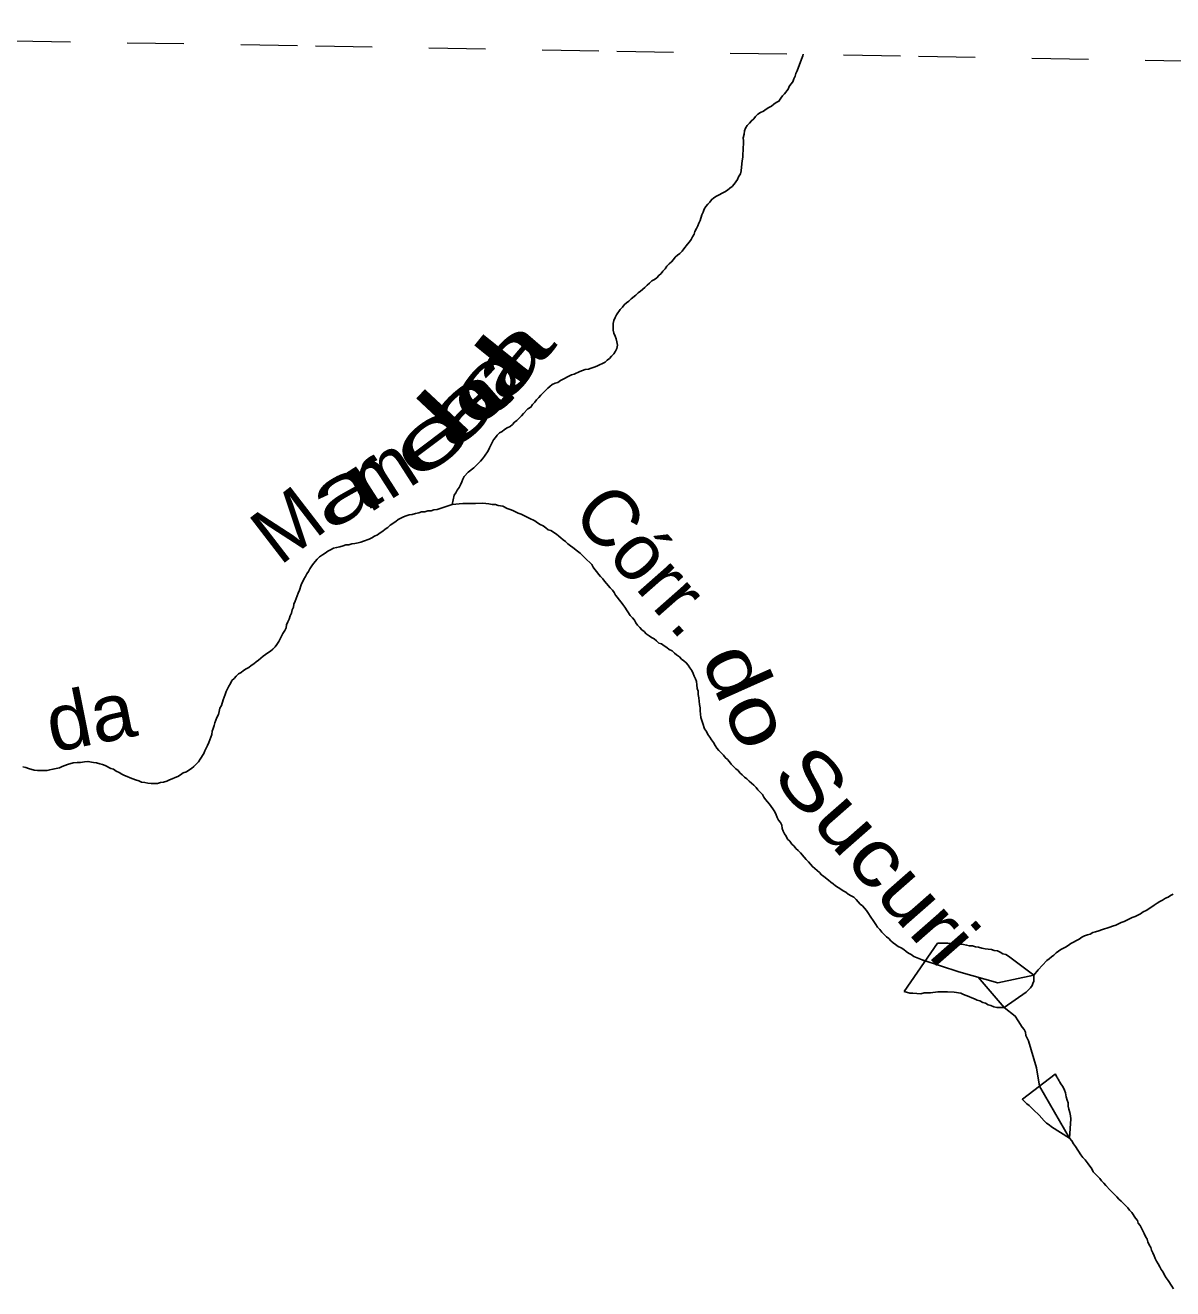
# Model space of a CAD drawing. Extents: x 785.9 to 812.4, y 7674.9 to 7703.1.
# Drawn here: x 787.987 to 790.01, y 7700.827 to 7703.055 of the extents above; entities that cross this region are included whole.
import ezdxf
from ezdxf.enums import TextEntityAlignment as Align

# ---------------------------------------------------------------- set-up
doc = ezdxf.new("R2010")
doc.units = 0
doc.header["$LTSCALE"] = 0.04
doc.linetypes.add('SHORT_DASHED', pattern=[2.7, 1.5, -1.2])
for name, color, linetype, lineweight in [('2', 7, 'Continuous', 25), ('53', 7, 'SHORT_DASHED', 13), ('55', 7, 'Continuous', 25), ('7', 7, 'Continuous', 25)]:
    doc.layers.add(name, color=color, linetype=linetype, lineweight=lineweight)
doc.layers.add('61', color=7, linetype='Continuous')

msp = doc.modelspace()

# ---------------------------------------------------------------- linework, layer by layer
at = {"layer": '2'}
for p, q in [((789.7451, 7701.1615), (789.8032, 7701.2055)), ((789.8032, 7701.2056), (789.8033, 7701.2055))]:
    msp.add_line(p, q, dxfattribs=at)
for points in [[(789.7654, 7701.3801), (789.7205, 7701.4139), (789.7157, 7701.4163), (789.7108, 7701.4179), (789.706, 7701.4204), (789.7011, 7701.4228), (789.6955, 7701.4236), (789.6906, 7701.4252), (789.6849, 7701.426), (789.6793, 7701.4268), (789.6736, 7701.4276), (789.6679, 7701.4293), (789.6623, 7701.4301), (789.6574, 7701.4317), (789.6518, 7701.4317), (789.6469, 7701.4333), (789.6412, 7701.4341), (789.6251, 7701.4349), (789.6194, 7701.4357), (789.6137, 7701.4365), (789.6081, 7701.4365), (789.6065, 7701.4365), (789.6048, 7701.4365), (789.6032, 7701.4365), (789.6016, 7701.4365), (789.6, 7701.4365), (789.5984, 7701.4365), (789.5967, 7701.4365), (789.5956, 7701.4365), (789.5365, 7701.3516)], [(789.7133, 7701.3233), (789.7521, 7701.35), (789.7594, 7701.3581), (789.7626, 7701.3621), (789.7642, 7701.367), (789.7651, 7701.3687), (789.7654, 7701.3801)], [(789.5365, 7701.3516), (789.5466, 7701.3483), (789.5522, 7701.3483), (789.566, 7701.3475), (789.5717, 7701.3492), (789.583, 7701.3492), (789.5959, 7701.3508), (789.6129, 7701.3508), (789.6251, 7701.35), (789.6364, 7701.3483), (789.6412, 7701.3459), (789.651, 7701.3427), (789.6558, 7701.3403), (789.6607, 7701.3386), (789.6655, 7701.3362), (789.6704, 7701.3346), (789.6752, 7701.3322), (789.6801, 7701.3305), (789.6849, 7701.3281), (789.6898, 7701.3265), (789.6946, 7701.3241), (789.7003, 7701.3233), (789.7133, 7701.3233)], [(789.8033, 7701.2054), (789.8061, 7701.2003), (789.807, 7701.1989), (789.8078, 7701.1975), (789.8086, 7701.1961), (789.8095, 7701.1947), (789.8103, 7701.1933), (789.8111, 7701.192), (789.812, 7701.1906), (789.8168, 7701.1825), (789.8193, 7701.1776), (789.8209, 7701.1728), (789.8225, 7701.1655), (789.8241, 7701.1598), (789.8257, 7701.155), (789.8257, 7701.1493), (789.8273, 7701.1436), (789.829, 7701.138), (789.8298, 7701.1323), (789.8306, 7701.1266), (789.8281, 7701.0929)], [(789.8281, 7701.0929), (789.7966, 7701.1129), (789.7926, 7701.1161), (789.7877, 7701.1194), (789.7837, 7701.1234), (789.7748, 7701.1331), (789.765, 7701.1428), (789.761, 7701.1461), (789.757, 7701.1501), (789.7529, 7701.1533), (789.7521, 7701.1542), (789.7449, 7701.1614), (789.7451, 7701.1615)]]:
    msp.add_lwpolyline(points, dxfattribs=at)
at = {"layer": '53'}
msp.add_lwpolyline([(786.3721, 7703.0549), (786.9037, 7703.0458), (787.4353, 7703.0367), (787.9669, 7703.0276), (788.4985, 7703.0185), (789.0301, 7703.0094), (789.5618, 7703.0003), (790.0934, 7702.9911), (790.625, 7702.9819), (791.1566, 7702.9727), (791.6883, 7702.9635), (792.2199, 7702.9543), (792.7515, 7702.9451), (793.2832, 7702.9358), (793.8148, 7702.9265), (794.3464, 7702.9173)], dxfattribs=at)
at = {"layer": '55'}
for p, q in [((789.7133, 7701.3233), (789.667, 7701.3766)), ((789.8281, 7701.0929), (789.7756, 7701.1847))]:
    msp.add_line(p, q, dxfattribs=at)
msp.add_lwpolyline([(789.5684, 7701.4074), (789.6329, 7701.3861), (789.7021, 7701.3667), (789.7654, 7701.3801)], dxfattribs=at)
at = {"layer": '7'}
for p, q in [((789.7654, 7701.3801), (789.7731, 7701.3896)), ((789.7699, 7701.2165), (789.7756, 7701.1847))]:
    msp.add_line(p, q, dxfattribs=at)
for points in [[(789.0239, 7702.5289), (789.0247, 7702.5346), (789.0271, 7702.5394), (789.0295, 7702.5443), (789.036, 7702.554), (789.0401, 7702.558), (789.0433, 7702.5621), (789.0473, 7702.5653), (789.0514, 7702.5685), (789.0554, 7702.5726), (789.0635, 7702.5791), (789.0676, 7702.5831), (789.0716, 7702.5863), (789.0797, 7702.5928), (789.0837, 7702.5969), (789.0878, 7702.6001), (789.0918, 7702.6041), (789.0967, 7702.6066), (789.1007, 7702.6098), (789.104, 7702.6138), (789.108, 7702.6171), (789.1113, 7702.6211), (789.1153, 7702.6252), (789.1185, 7702.63), (789.1226, 7702.6341), (789.1266, 7702.6381), (789.1299, 7702.6422), (789.1331, 7702.6462), (789.1371, 7702.6495), (789.1412, 7702.6527), (789.1452, 7702.6567), (789.1485, 7702.6608), (789.1549, 7702.6689), (789.1582, 7702.6729), (789.1614, 7702.677), (789.1638, 7702.6818), (789.1663, 7702.6867), (789.1679, 7702.6915), (789.1703, 7702.6964), (789.1727, 7702.7012), (789.1744, 7702.7061), (789.1768, 7702.7109), (789.18, 7702.7207), (789.1825, 7702.7255), (789.1841, 7702.7304), (789.1873, 7702.7352), (789.1906, 7702.7393), (789.1938, 7702.7433), (789.197, 7702.7474), (789.2011, 7702.7506), (789.2059, 7702.7538), (789.2205, 7702.7611), (789.2253, 7702.7644), (789.2294, 7702.7676), (789.2334, 7702.7708), (789.2367, 7702.7749), (789.2399, 7702.7789), (789.2431, 7702.783), (789.2448, 7702.7878), (789.248, 7702.7927), (789.2496, 7702.7983), (789.2504, 7702.8105), (789.2512, 7702.8161), (789.252, 7702.8226), (789.252, 7702.8283), (789.2529, 7702.8339), (789.2529, 7702.8396), (789.2537, 7702.8453), (789.2537, 7702.8509), (789.2529, 7702.8566), (789.2545, 7702.8631), (789.2553, 7702.8687), (789.2569, 7702.8736), (789.2601, 7702.8784), (789.2642, 7702.8825), (789.2674, 7702.8865), (789.2715, 7702.8898), (789.2747, 7702.8938), (789.2787, 7702.8979), (789.2836, 7702.9011), (789.2885, 7702.9035), (789.2933, 7702.9068), (789.2982, 7702.91), (789.303, 7702.9124), (789.3071, 7702.9157), (789.3111, 7702.9189), (789.316, 7702.9213), (789.3192, 7702.9262), (789.3224, 7702.9302), (789.3257, 7702.9343), (789.3322, 7702.9424), (789.3338, 7702.9472), (789.337, 7702.9513), (789.3402, 7702.9553), (789.3419, 7702.9602), (789.3443, 7702.965), (789.3459, 7702.9699), (789.3483, 7702.9747), (789.3556, 7702.995), (789.3578, 7703.001), (789.3585, 7703.0038)], [(788.7399, 7702.2101), (788.7431, 7702.2263), (788.7463, 7702.2303), (788.7488, 7702.2352), (788.752, 7702.24), (788.7544, 7702.2449), (788.7568, 7702.2497), (788.7585, 7702.2546), (788.7609, 7702.2594), (788.7682, 7702.2667), (788.7779, 7702.2748), (788.7819, 7702.2789), (788.786, 7702.2829), (788.79, 7702.2861), (788.7933, 7702.2902), (788.7965, 7702.295), (788.803, 7702.3048), (788.8054, 7702.3096), (788.8078, 7702.3145), (788.8103, 7702.3193), (788.8127, 7702.3242), (788.8159, 7702.3282), (788.8192, 7702.3323), (788.8232, 7702.3363), (788.8281, 7702.3387), (788.8321, 7702.342), (788.837, 7702.3452), (788.8418, 7702.3476), (788.8459, 7702.3509), (788.8499, 7702.3549), (788.8539, 7702.3582), (788.862, 7702.3663), (788.8653, 7702.3703), (788.8734, 7702.3784), (788.8782, 7702.3816), (788.8815, 7702.3865), (788.8855, 7702.3905), (788.8887, 7702.3946), (788.8928, 7702.3986), (788.896, 7702.4027), (788.9082, 7702.4148), (788.9122, 7702.418), (788.9163, 7702.4213), (788.9211, 7702.4237), (788.926, 7702.4253), (788.9308, 7702.4286), (788.9502, 7702.4383), (788.9551, 7702.4399), (788.9648, 7702.4447), (788.9697, 7702.4464), (788.9745, 7702.448), (788.9802, 7702.4488), (788.985, 7702.4504), (788.9899, 7702.452), (788.9947, 7702.4536), (789.0093, 7702.4609), (789.0133, 7702.4642), (789.0174, 7702.4674), (789.0206, 7702.4714), (789.0247, 7702.4755), (789.0279, 7702.4803), (789.0303, 7702.4852), (789.0311, 7702.4909), (789.0303, 7702.4965), (789.0287, 7702.5022), (789.0271, 7702.507), (789.0247, 7702.5119), (789.0239, 7702.5176), (789.0239, 7702.5289)], [(788.3248, 7701.8346), (788.328, 7701.8395), (788.3288, 7701.8452), (788.3304, 7701.8508), (788.3329, 7701.8557), (788.3361, 7701.8654), (788.3377, 7701.8702), (788.3393, 7701.8751), (788.341, 7701.88), (788.3434, 7701.8848), (788.3458, 7701.8897), (788.349, 7701.8945), (788.3515, 7701.8994), (788.3555, 7701.9034), (788.3588, 7701.9075), (788.3628, 7701.9115), (788.3677, 7701.9139), (788.3717, 7701.9172), (788.3766, 7701.9204), (788.3814, 7701.9228), (788.3855, 7701.9261), (788.3903, 7701.9293), (788.3944, 7701.9326), (788.3984, 7701.9358), (788.4024, 7701.939), (788.4065, 7701.9423), (788.4105, 7701.9455), (788.4146, 7701.9487), (788.4194, 7701.9512), (788.4235, 7701.9552), (788.4275, 7701.9593), (788.4308, 7701.9633), (788.434, 7701.9682), (788.4364, 7701.973), (788.4389, 7701.9779), (788.4413, 7701.9827), (788.4445, 7701.9876), (788.4469, 7701.9924), (788.4478, 7701.9981), (788.4502, 7702.0029), (788.4526, 7702.0078), (788.4542, 7702.0135), (788.4567, 7702.0183), (788.4575, 7702.024), (788.4599, 7702.0288), (788.4607, 7702.0345), (788.4631, 7702.0394), (788.4647, 7702.0442), (788.468, 7702.0539), (788.4704, 7702.0588), (788.4736, 7702.0685), (788.4785, 7702.0782), (788.4809, 7702.0831), (788.4834, 7702.0879), (788.4866, 7702.092), (788.489, 7702.0968), (788.4923, 7702.1017), (788.4955, 7702.1057), (788.502, 7702.1138), (788.506, 7702.1178), (788.5109, 7702.1211), (788.5157, 7702.1243), (788.5206, 7702.1276), (788.5254, 7702.13), (788.5303, 7702.1332), (788.536, 7702.134), (788.5416, 7702.1356), (788.5473, 7702.1373), (788.5521, 7702.1389), (788.5578, 7702.1389), (788.5627, 7702.1405), (788.5683, 7702.1413), (788.574, 7702.1421), (788.5788, 7702.1437), (788.5837, 7702.1454), (788.5934, 7702.1486), (788.5983, 7702.151), (788.6031, 7702.1543), (788.608, 7702.1567), (788.6128, 7702.1599), (788.6177, 7702.1632), (788.6217, 7702.1664), (788.6266, 7702.1696), (788.6306, 7702.1737), (788.6403, 7702.1801), (788.6444, 7702.1834), (788.6541, 7702.1882), (788.6589, 7702.1899), (788.6638, 7702.1915), (788.6695, 7702.1923), (788.6751, 7702.1939), (788.6808, 7702.1955), (788.6856, 7702.1971), (788.6913, 7702.1971), (788.697, 7702.1988), (788.7026, 7702.1988), (788.7075, 7702.2004), (788.7132, 7702.2012), (788.7188, 7702.2028), (788.7237, 7702.2044), (788.7399, 7702.2101)], [(788.7399, 7702.2101), (788.7585, 7702.2117), (788.7811, 7702.2117), (788.7933, 7702.2125), (788.7989, 7702.2117), (788.8046, 7702.2109), (788.8103, 7702.2101), (788.8159, 7702.2101), (788.8208, 7702.2085), (788.8289, 7702.2069), (788.837, 7702.2028), (788.8418, 7702.2012), (788.8467, 7702.1996), (788.8564, 7702.1947), (788.8612, 7702.1931), (788.8709, 7702.1882), (788.8758, 7702.1858), (788.8855, 7702.181), (788.8904, 7702.1777), (788.8952, 7702.1745), (788.9001, 7702.1721), (788.9049, 7702.1688), (788.909, 7702.1656), (788.9138, 7702.164), (788.9235, 7702.1575), (788.9276, 7702.1543), (788.9316, 7702.151), (788.9357, 7702.1478), (788.9397, 7702.1445), (788.9438, 7702.1405), (788.9486, 7702.1373), (788.9527, 7702.134), (788.9608, 7702.1276), (788.9656, 7702.1243), (788.9697, 7702.1203), (788.9737, 7702.1162), (788.9858, 7702.1041), (788.9883, 7702.0992), (788.9915, 7702.0952), (788.9947, 7702.0911), (788.998, 7702.0871), (789.0012, 7702.0831), (789.0053, 7702.079), (789.0085, 7702.075), (789.0117, 7702.0709), (789.0182, 7702.0628), (789.0222, 7702.0588), (789.0255, 7702.0547), (789.0279, 7702.0499), (789.0311, 7702.0458), (789.0344, 7702.0418), (789.0376, 7702.0377), (789.0409, 7702.0337), (789.0441, 7702.0288), (789.0538, 7702.0143), (789.0579, 7702.0102), (789.0611, 7702.0062), (789.0635, 7702.0013), (789.0668, 7701.9973), (789.0708, 7701.9932), (789.074, 7701.9892), (789.0781, 7701.986), (789.0821, 7701.9819), (789.087, 7701.9787), (789.091, 7701.9754), (789.0959, 7701.973), (789.0999, 7701.9698), (789.104, 7701.9657), (789.1088, 7701.9641), (789.1137, 7701.9609), (789.1185, 7701.9576), (789.1226, 7701.9544), (789.1274, 7701.952), (789.1315, 7701.9479), (789.1355, 7701.9447), (789.1404, 7701.9415), (789.1444, 7701.9374), (789.1485, 7701.9342), (789.1525, 7701.9309), (789.1558, 7701.9269), (789.159, 7701.922), (789.1622, 7701.9172), (789.1647, 7701.9123), (789.1663, 7701.9075), (789.1687, 7701.9026), (789.1703, 7701.8978), (789.1711, 7701.8921), (789.1719, 7701.8856), (789.1736, 7701.8808), (789.1736, 7701.8751), (789.1744, 7701.8694), (789.1752, 7701.863), (789.176, 7701.8573), (789.1768, 7701.8516), (789.1768, 7701.846), (789.1776, 7701.8403), (789.1784, 7701.8346), (789.18, 7701.829), (789.1817, 7701.8241), (789.1849, 7701.8144), (789.1881, 7701.8096)], [(787.9825, 7701.7473), (787.9882, 7701.7464), (787.993, 7701.7448), (788.0027, 7701.7416), (788.0084, 7701.7408), (788.0254, 7701.7408), (788.0302, 7701.7424), (788.0359, 7701.7432), (788.0416, 7701.7448), (788.0472, 7701.7456), (788.0521, 7701.7481), (788.0569, 7701.7497), (788.0618, 7701.7513), (788.0715, 7701.7545), (788.0788, 7701.7553), (788.0845, 7701.7553), (788.0917, 7701.7562), (788.0974, 7701.757), (788.1071, 7701.7553), (788.1128, 7701.7545), (788.1184, 7701.7529), (788.1233, 7701.7513), (788.1281, 7701.7497), (788.1379, 7701.7448), (788.1427, 7701.7432), (788.1476, 7701.74), (788.1524, 7701.7375), (788.1573, 7701.7343), (788.1621, 7701.7319), (788.167, 7701.7303), (788.1718, 7701.7278), (788.1767, 7701.7262), (788.1815, 7701.7246), (788.1872, 7701.723), (788.1921, 7701.7206), (788.1977, 7701.7197), (788.2034, 7701.7189), (788.2091, 7701.7181), (788.2204, 7701.7181), (788.2252, 7701.7197), (788.2309, 7701.7206), (788.2366, 7701.7222), (788.2414, 7701.7246), (788.2463, 7701.7262), (788.2511, 7701.7286), (788.256, 7701.7303), (788.2608, 7701.7335), (788.2657, 7701.7367), (788.2714, 7701.7384), (788.2754, 7701.7416), (788.2803, 7701.7448), (788.2843, 7701.7481), (788.2924, 7701.7562), (788.2956, 7701.761), (788.3021, 7701.7707), (788.3037, 7701.7756), (788.3062, 7701.7804), (788.3086, 7701.7853), (788.311, 7701.7901), (788.3126, 7701.795), (788.3142, 7701.7999), (788.3159, 7701.8047), (788.3167, 7701.8104), (788.3183, 7701.8152), (788.3199, 7701.8201), (788.3215, 7701.8249), (788.3231, 7701.8298), (788.3248, 7701.8346)], [(789.1881, 7701.8096), (789.1906, 7701.8047), (789.1938, 7701.7999), (789.197, 7701.795), (789.2003, 7701.7901), (789.2035, 7701.7853), (789.2067, 7701.7804), (789.21, 7701.7764), (789.214, 7701.7723), (789.2181, 7701.7683), (789.2213, 7701.7642), (789.2253, 7701.7602), (789.2286, 7701.7562), (789.2318, 7701.7521), (789.2359, 7701.7481), (789.2399, 7701.744), (789.244, 7701.7408), (789.2472, 7701.7367), (789.2512, 7701.7335), (789.2553, 7701.7295), (789.2593, 7701.7262), (789.2634, 7701.7222), (789.2674, 7701.7189), (789.2715, 7701.7149), (789.2755, 7701.7108), (789.2787, 7701.7068), (789.2828, 7701.7028), (789.2868, 7701.6987), (789.2893, 7701.6939), (789.2925, 7701.6898), (789.2957, 7701.6858), (789.299, 7701.6817), (789.3022, 7701.6777), (789.3054, 7701.6736), (789.3087, 7701.668), (789.3111, 7701.6631), (789.3127, 7701.6583), (789.3152, 7701.6534), (789.3184, 7701.6494), (789.3208, 7701.6445), (789.3216, 7701.6388), (789.3233, 7701.634), (789.3257, 7701.6291), (789.3289, 7701.6251), (789.3313, 7701.6202), (789.3354, 7701.6162), (789.3386, 7701.6113), (789.3427, 7701.6073), (789.3459, 7701.6032), (789.35, 7701.6), (789.354, 7701.5959), (789.3605, 7701.5879), (789.3637, 7701.5838), (789.3678, 7701.5798), (789.3718, 7701.5757), (789.375, 7701.5717), (789.3791, 7701.5684), (789.3831, 7701.5644), (789.3872, 7701.5612), (789.3912, 7701.5571), (789.3953, 7701.5539), (789.4034, 7701.5474), (789.4074, 7701.5442), (789.4114, 7701.5409), (789.4155, 7701.5377), (789.4203, 7701.5345), (789.4252, 7701.532), (789.4292, 7701.5288), (789.4341, 7701.5264), (789.4381, 7701.5231), (789.443, 7701.5199), (789.4479, 7701.5175), (789.4519, 7701.5134), (789.4559, 7701.5094), (789.4592, 7701.5053), (789.4632, 7701.5021), (789.4665, 7701.498), (789.4705, 7701.494), (789.4738, 7701.4891), (789.477, 7701.4843), (789.4835, 7701.4746), (789.4867, 7701.4697), (789.4899, 7701.4649), (789.494, 7701.4608), (789.4972, 7701.456), (789.5013, 7701.4519), (789.5053, 7701.4479), (789.5094, 7701.4446), (789.5134, 7701.4406), (789.5174, 7701.4374), (789.5215, 7701.4341), (789.5263, 7701.4309), (789.5312, 7701.4285), (789.5361, 7701.4252), (789.5401, 7701.422), (789.5441, 7701.4187), (789.549, 7701.4163), (789.5539, 7701.4131), (789.5684, 7701.4074), (789.5734, 7701.4046)], [(789.9536, 7701.4883), (789.9584, 7701.4916), (789.9633, 7701.494), (789.9681, 7701.4972), (789.9778, 7701.5037), (789.9827, 7701.5069), (789.9876, 7701.5102), (789.9924, 7701.5126), (789.9973, 7701.5158), (790.0021, 7701.5175), (790.0062, 7701.5207), (790.011, 7701.5231)], [(789.7731, 7701.3896), (789.7885, 7701.4058), (789.7926, 7701.409), (789.7966, 7701.4123), (789.8006, 7701.4155), (789.8047, 7701.4196), (789.8128, 7701.4252), (789.8209, 7701.4293), (789.8257, 7701.4325), (789.8306, 7701.4357), (789.8354, 7701.4382), (789.8403, 7701.4414), (789.8451, 7701.4438), (789.85, 7701.4471), (789.8549, 7701.4495), (789.8597, 7701.4511), (789.8646, 7701.4527), (789.8694, 7701.4552), (789.8743, 7701.4568), (789.8799, 7701.4584), (789.8848, 7701.46), (789.8994, 7701.4649), (789.9042, 7701.4665), (789.9099, 7701.4681), (789.9196, 7701.473), (789.9244, 7701.4746), (789.939, 7701.4819), (789.9439, 7701.4835), (789.9536, 7701.4883)], [(789.7699, 7701.2165), (789.7561, 7701.2642), (789.7513, 7701.2739), (789.7505, 7701.2796), (789.7481, 7701.2844), (789.7448, 7701.2885), (789.7375, 7701.2998), (789.7327, 7701.3079), (789.7133, 7701.3233)], [(789.8281, 7701.0929), (789.8322, 7701.0878), (789.8354, 7701.083), (789.8387, 7701.0781), (789.8484, 7701.0635), (789.8516, 7701.0587), (789.8557, 7701.0546), (789.8613, 7701.0473), (789.8678, 7701.0384), (789.8702, 7701.0336), (789.8743, 7701.0295), (789.8775, 7701.0255), (789.8816, 7701.0215), (789.8848, 7701.0174), (789.8888, 7701.0134), (789.8921, 7701.0093), (789.9002, 7701.0012), (789.9042, 7700.9972), (789.9083, 7700.9931), (789.9115, 7700.9891), (789.9155, 7700.985), (789.9196, 7700.9818), (789.9277, 7700.9737), (789.9309, 7700.9697), (789.9342, 7700.9656), (789.9382, 7700.9616), (789.9447, 7700.9519), (789.9479, 7700.9478), (789.9495, 7700.943), (789.9528, 7700.9389), (789.9576, 7700.9292), (789.96, 7700.9244), (789.9625, 7700.9195), (789.9649, 7700.9146), (789.9665, 7700.9098), (789.9689, 7700.9049), (789.9714, 7700.9001), (789.973, 7700.8952), (789.9754, 7700.8904), (789.9778, 7700.8855), (789.9795, 7700.8807), (789.9819, 7700.8758), (789.9843, 7700.871), (789.9876, 7700.8661), (789.99, 7700.8612), (789.9932, 7700.8564), (789.9956, 7700.8515), (789.9989, 7700.8467), (790.0021, 7700.8418), (790.0086, 7700.8321), (790.0118, 7700.8273)]]:
    msp.add_lwpolyline(points, dxfattribs=at)

# ---------------------------------------------------------------- texts
at = {"layer": '61'}
for s, rotation, width, p in [('d', 51.23, 2.15, (788.8388, 7702.3969)), ('a', 49.189, 1.95, (788.8786, 7702.4363)), ('a', 41.221, 2, (788.7941, 7702.3485)), ('l', 46.932, 1.9, (788.761, 7702.3332)), ('e', 36.923, 1.85, (788.7294, 7702.288)), ('r', 32.626, 1.7, (788.6148, 7702.2144)), ('a', 28.328, 1.55, (788.57, 7702.1893)), ('do', 294.091, 1.25, (789.2151, 7701.8537)), ('da', 11.284, 1.05, (788.1113, 7701.7877)), ('Sucuri', 311.27, 1.2, (789.4504, 7701.5591))]:
    msp.add_text(s, height=0.1, rotation=rotation, dxfattribs=dict(at, width=width)).set_placement(p, align=Align.CENTER)
for s, rotation, p in [('m', 32.626, (788.6412, 7702.2242)), ('M', 37.604, (788.48, 7702.1347)), ('Córr.', 311.409, (789.0462, 7702.0794))]:
    msp.add_text(s, height=0.1, rotation=rotation, dxfattribs=at).set_placement(p, align=Align.CENTER)

doc.saveas('drawing.dxf')
